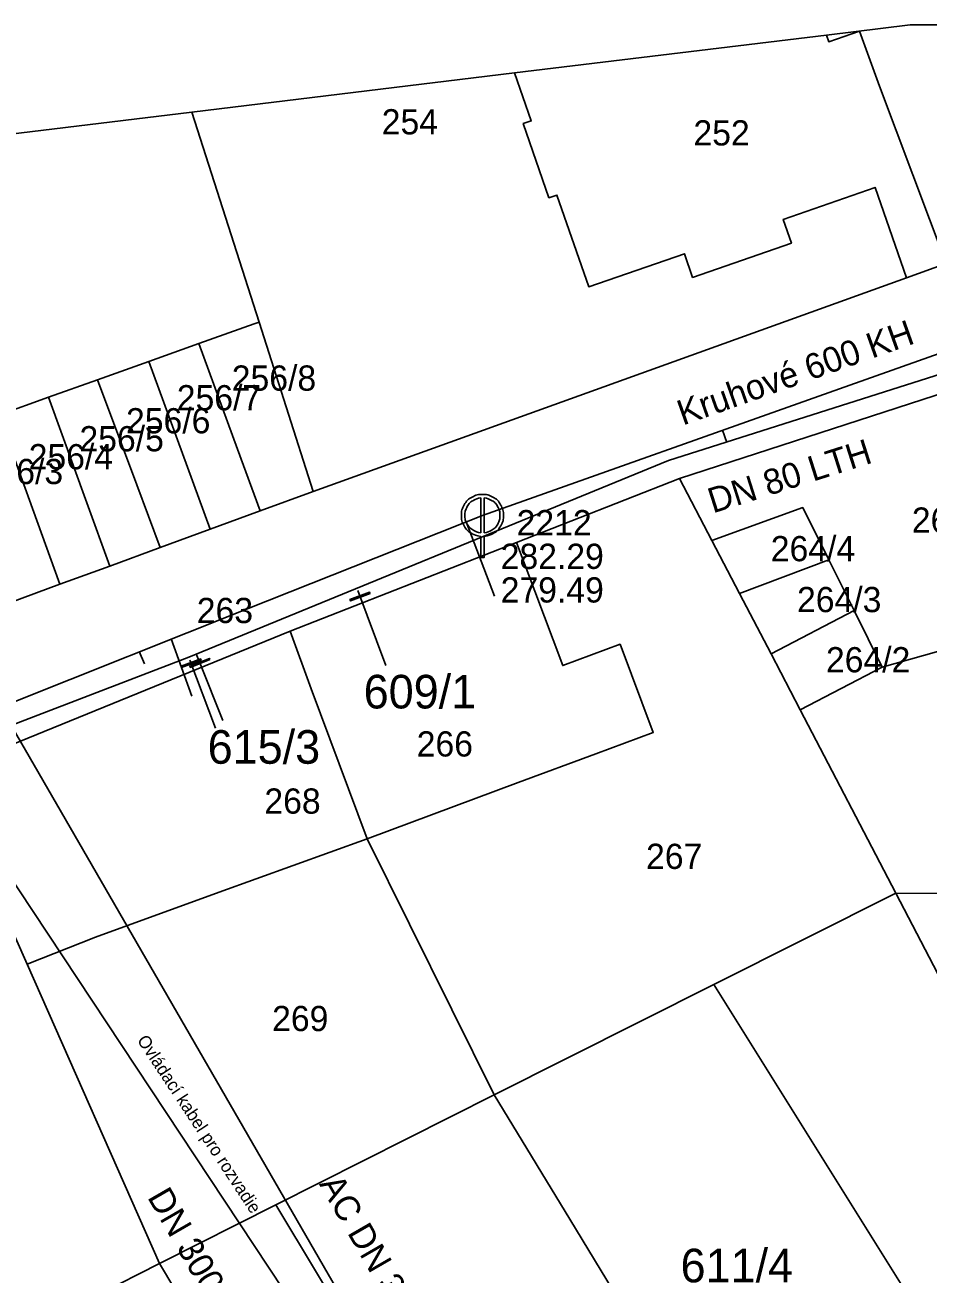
# Model space of a CAD drawing. Extents: x -571312 to -571060, y -1087128 to -1086933.
# Drawn here: x -571207.6 to -571153.9, y -1087007.2 to -1086932.9 of the extents above; entities that cross this region are included whole.
import ezdxf

# ---------------------------------------------------------------- set-up
doc = ezdxf.new("R2010")
doc.units = 0
for name, color, linetype in [('Adresní místo-text', 7, 'Continuous'), ('Armatura vodovodní', 7, 'Continuous'), ('Default', 7, 'Continuous'), ('Elektro NN - vedení', 7, 'Continuous'), ('Elektro VN_ VVN - popis', 7, 'Continuous'), ('Kanalizační přípojka', 7, 'Continuous'), ('Kanalizační stoka', 7, 'Continuous'), ('Kanalizační šachta', 7, 'Continuous'), ('Parcela-polygon', 7, 'Continuous'), ('Parcela-text', 7, 'Continuous'), ('Popis kmenové stoky', 7, 'Continuous'), ('Popis šachty', 7, 'Continuous'), ('Vodovodní přípojka', 7, 'Continuous'), ('Vodovodní řad', 7, 'Continuous'), ('Řad vodovodní popis', 7, 'Continuous')]:
    doc.layers.add(name, color=color, linetype=linetype)

msp = doc.modelspace()

# ---------------------------------------------------------------- linework, layer by layer
at = {"layer": 'Armatura vodovodní'}
for points in [[(-571187.124, -1086966.71), (-571188.295, -1086967.148), (-571188.323, -1086967.075), (-571187.152, -1086966.637), (-571187.124, -1086966.71)], [(-571197.17, -1086970.679), (-571198.342, -1086971.116), (-571198.369, -1086971.043), (-571197.198, -1086970.606), (-571197.17, -1086970.679)], [(-571196.655, -1086970.643), (-571197.817, -1086971.103), (-571197.846, -1086971.03), (-571196.683, -1086970.57), (-571196.655, -1086970.643)]]:
    msp.add_lwpolyline(points, dxfattribs=at)
at = {"layer": 'Default'}
for points in [[(-571180.543, -1086963.308), (-571180.801, -1086963.29), (-571181.063, -1086963.144), (-571181.36, -1086962.98), (-571181.525, -1086962.683), (-571181.69, -1086962.385), (-571181.69, -1086962.06), (-571181.69, -1086961.733), (-571181.522, -1086961.433), (-571181.353, -1086961.132), (-571181.055, -1086960.971), (-571180.757, -1086960.81), (-571180.44, -1086960.81), (-571180.125, -1086960.81), (-571179.826, -1086960.971), (-571179.527, -1086961.132), (-571179.358, -1086961.433), (-571179.19, -1086961.733), (-571179.19, -1086962.06), (-571179.19, -1086962.385), (-571179.355, -1086962.683), (-571179.52, -1086962.98), (-571179.817, -1086963.144), (-571180.079, -1086963.29), (-571180.337, -1086963.308)], [(-571180.543, -1086961.022), (-571180.74, -1086961.039), (-571180.955, -1086961.154), (-571181.204, -1086961.289), (-571181.343, -1086961.539), (-571181.482, -1086961.789), (-571181.482, -1086962.06), (-571181.482, -1086962.331), (-571181.346, -1086962.578), (-571181.209, -1086962.824), (-571180.96, -1086962.961), (-571180.748, -1086963.081), (-571180.543, -1086963.095)], [(-571180.337, -1086963.095), (-571180.132, -1086963.081), (-571179.918, -1086962.961), (-571179.671, -1086962.824), (-571179.534, -1086962.578), (-571179.398, -1086962.331), (-571179.398, -1086962.06), (-571179.398, -1086961.789), (-571179.538, -1086961.539), (-571179.678, -1086961.289), (-571179.927, -1086961.154), (-571180.14, -1086961.039), (-571180.337, -1086961.022)]]:
    msp.add_open_spline(points, degree=3, dxfattribs=at)
at = {"layer": 'Elektro NN - vedení'}
msp.add_lwpolyline([(-571071.926, -1087014.396), (-571073.5, -1087015.707), (-571083.992, -1087003.116), (-571092.911, -1086996.034), (-571095.272, -1086994.46), (-571113.896, -1086998.657), (-571175.538, -1087035.118), (-571177.374, -1087030.659), (-571213.311, -1086976.361), (-571216.983, -1086969.541), (-571228.263, -1086944.884), (-571229.263, -1086941.883)], dxfattribs=at)
at = {"layer": 'Kanalizační přípojka'}
for points in [[(-571165.9, -1086957.73), (-571166.159, -1086956.998)], [(-571179.73, -1086966.87), (-571181.403, -1086962.442)], [(-571197.72, -1086972.82), (-571198.961, -1086969.413)], [(-571200.55, -1086970.9), (-571200.865, -1086970.169)]]:
    msp.add_lwpolyline(points, dxfattribs=at)
at = {"layer": 'Kanalizační stoka'}
for points in [[(-571180.44, -1086962.06), (-571159.195, -1086954.53), (-571137.95, -1086947)], [(-571208.5, -1086973.24), (-571194.47, -1086967.65), (-571180.44, -1086962.06)]]:
    msp.add_lwpolyline(points, dxfattribs=at)
at = {"layer": 'Kanalizační šachta'}
for points in [[(-571180.543, -1086963.095), (-571180.543, -1086961.022)], [(-571180.337, -1086961.022), (-571180.337, -1086963.095)], [(-571180.337, -1086963.308), (-571180.337, -1086964.56), (-571180.543, -1086964.56), (-571180.543, -1086963.308)]]:
    msp.add_lwpolyline(points, dxfattribs=at)
at = {"layer": 'Parcela-polygon'}
for p, q in [((-571154.996, -1086932.879), (-571159.977, -1086933.483)), ((-571122.956, -1086932.879), (-571154.996, -1086932.879)), ((-571159.977, -1086933.483), (-571178.531, -1086935.733)), ((-571178.531, -1086935.733), (-571197.723, -1086938.059)), ((-571197.723, -1086938.059), (-571223.423, -1086941.175))]:
    msp.add_line(p, q, dxfattribs=at)
for points in [[(-571178.531, -1086935.733), (-571177.54, -1086938.59), (-571178.01, -1086938.75), (-571176.49, -1086943.16), (-571176.01, -1086943), (-571174.12, -1086948.46), (-571168.43, -1086946.49), (-571167.94, -1086947.9), (-571162.06, -1086945.86), (-571162.55, -1086944.45), (-571157.09, -1086942.55), (-571155.22, -1086947.92), (-571152.86, -1086947.07), (-571156.82, -1086936.52), (-571158.01, -1086933.25), (-571159.84, -1086933.88), (-571159.977, -1086933.483)], [(-571159.977, -1086933.483), (-571159.84, -1086933.88), (-571158.01, -1086933.25), (-571156.82, -1086936.52), (-571152.86, -1086947.07), (-571140.74, -1086942.7), (-571124.19, -1086936.69), (-571122.956, -1086932.879)], [(-571197.723, -1086938.059), (-571193.73, -1086950.56), (-571190.51, -1086960.64), (-571155.22, -1086947.92), (-571157.09, -1086942.55), (-571162.55, -1086944.45), (-571162.06, -1086945.86), (-571167.94, -1086947.9), (-571168.43, -1086946.49), (-571174.12, -1086948.46), (-571176.01, -1086943), (-571176.49, -1086943.16), (-571178.01, -1086938.75), (-571177.54, -1086938.59), (-571178.531, -1086935.733)], [(-571223.423, -1086941.175), (-571223.15, -1086941.67), (-571214.21, -1086957.87), (-571212.16, -1086957.14), (-571209.22, -1086956.09), (-571206.25, -1086955.03), (-571203.34, -1086954), (-571200.29, -1086952.91), (-571197.31, -1086951.84), (-571194.02, -1086950.67), (-571193.73, -1086950.56), (-571197.723, -1086938.059)], [(-571152.86, -1086947.07), (-571155.22, -1086947.92), (-571190.51, -1086960.64), (-571193.66, -1086961.8), (-571196.64, -1086962.89), (-571199.6, -1086963.98), (-571202.6, -1086965.08), (-571205.57, -1086966.16), (-571208.52, -1086967.25), (-571211.54, -1086968.35), (-571214.64, -1086969.49), (-571219.5, -1086971.02), (-571225.44, -1086972.88), (-571230.87, -1086974.59), (-571232.95, -1086975.24), (-571245.21, -1086979.4), (-571247.22, -1086979.94), (-571250.67, -1086980.27)], [(-571308.971, -1086951.546), (-571306.25, -1086957.27), (-571289.46, -1086969.43), (-571269.48, -1086983.31), (-571253.67, -1086989.56), (-571249.74, -1086991.11), (-571231.55, -1086984.26), (-571212.55, -1086977.39), (-571191.88, -1086968.96), (-571178.41, -1086963.67), (-571168.71, -1086959.87), (-571150.45, -1086953.94)], [(-571149.28, -1086969.01), (-571156.67, -1086971.09), (-571161.54, -1086973.63), (-571155.86, -1086984.54), (-571144.84, -1086984.62)], [(-571144.84, -1086984.62), (-571155.86, -1086984.54), (-571144.15, -1087007.02)]]:
    msp.add_lwpolyline(points, dxfattribs=at)
for points in [[(-571190.51, -1086960.64), (-571193.73, -1086950.56), (-571194.02, -1086950.67), (-571197.31, -1086951.84), (-571195.01, -1086958.13), (-571193.66, -1086961.8)], [(-571200.29, -1086952.91), (-571197.99, -1086959.19), (-571196.64, -1086962.89), (-571193.66, -1086961.8), (-571195.01, -1086958.13), (-571197.31, -1086951.84)], [(-571203.34, -1086954), (-571201, -1086960.25), (-571199.6, -1086963.98), (-571196.64, -1086962.89), (-571197.99, -1086959.19), (-571200.29, -1086952.91)], [(-571206.25, -1086955.03), (-571203.97, -1086961.31), (-571202.6, -1086965.08), (-571199.6, -1086963.98), (-571201, -1086960.25), (-571203.34, -1086954)], [(-571168.71, -1086959.87), (-571166.79, -1086963.56), (-571161.39, -1086961.6), (-571159.84, -1086964.71), (-571158.34, -1086967.73), (-571156.67, -1086971.09), (-571149.28, -1086969.01), (-571150.45, -1086953.94)], [(-571209.22, -1086956.09), (-571206.94, -1086962.36), (-571205.57, -1086966.16), (-571202.6, -1086965.08), (-571203.97, -1086961.31), (-571206.25, -1086955.03)], [(-571212.16, -1086957.14), (-571209.9, -1086963.41), (-571208.52, -1086967.25), (-571205.57, -1086966.16), (-571206.94, -1086962.36), (-571209.22, -1086956.09)], [(-571166.79, -1086963.56), (-571168.71, -1086959.87), (-571178.41, -1086963.67), (-571175.66, -1086971), (-571172.25, -1086969.73), (-571170.28, -1086974.98), (-571173.69, -1086976.25), (-571178.32, -1086977.96), (-571187.29, -1086981.31), (-571179.74, -1086996.54), (-571166.67, -1086989.97), (-571155.86, -1086984.54), (-571161.54, -1086973.63), (-571163.27, -1086970.3), (-571165.15, -1086966.71)], [(-571159.84, -1086964.71), (-571161.39, -1086961.6), (-571166.79, -1086963.56), (-571165.15, -1086966.71)], [(-571178.41, -1086963.67), (-571191.88, -1086968.96), (-571190.63, -1086972.39), (-571187.29, -1086981.31), (-571178.32, -1086977.96), (-571173.69, -1086976.25), (-571170.28, -1086974.98), (-571172.25, -1086969.73), (-571175.66, -1086971)], [(-571158.34, -1086967.73), (-571159.84, -1086964.71), (-571165.15, -1086966.71), (-571163.27, -1086970.3)], [(-571163.27, -1086970.3), (-571161.54, -1086973.63), (-571156.67, -1086971.09), (-571158.34, -1086967.73)], [(-571191.88, -1086968.96), (-571212.55, -1086977.39), (-571211.36, -1086980.09), (-571209.71, -1086983.81), (-571208.98, -1086985.45), (-571207.52, -1086988.77), (-571203.45, -1086987.16), (-571196.09, -1086984.48), (-571187.29, -1086981.31), (-571190.63, -1086972.39)], [(-571187.29, -1086981.31), (-571196.09, -1086984.48), (-571203.45, -1086987.16), (-571207.52, -1086988.77), (-571199.65, -1087006.57), (-571192.72, -1087003.08), (-571179.74, -1086996.54)], [(-571144.15, -1087007.02), (-571155.86, -1086984.54), (-571166.67, -1086989.97), (-571152.8, -1087012.2)], [(-571208.98, -1086985.45), (-571218.36, -1086988.9), (-571217.04, -1086992.42), (-571226.94, -1086996.1), (-571217.97, -1087015.93), (-571206.82, -1087010.23), (-571199.65, -1087006.57), (-571207.52, -1086988.77)], [(-571179.74, -1086996.54), (-571179.19, -1086997.45), (-571175.25, -1087003.94), (-571172.31, -1087008.78), (-571167.11, -1087017.33), (-571165.57, -1087019.85), (-571152.8, -1087012.2), (-571166.67, -1086989.97)], [(-571179.19, -1086997.45), (-571179.74, -1086996.54), (-571192.72, -1087003.08), (-571178.15, -1087027.35), (-571165.57, -1087019.85), (-571167.11, -1087017.33), (-571172.31, -1087008.78), (-571175.25, -1087003.94)], [(-571178.15, -1087027.35), (-571192.72, -1087003.08), (-571199.65, -1087006.57), (-571184.85, -1087031.35)], [(-571184.85, -1087031.35), (-571199.65, -1087006.57), (-571206.82, -1087010.23), (-571202.38, -1087017.63), (-571197.08, -1087017.54), (-571187.38, -1087032.88)]]:
    msp.add_lwpolyline(points, close=True, dxfattribs=at)
at = {"layer": 'Vodovodní přípojka'}
for p, q in [((-571186.19, -1086970.999), (-571187.855, -1086966.54)), ((-571196.325, -1086974.732), (-571197.838, -1086970.678))]:
    msp.add_line(p, q, dxfattribs=at)
msp.add_lwpolyline([(-571197.46, -1086970.307), (-571197.25, -1086970.837), (-571195.891, -1086974.271)], dxfattribs=at)
at = {"layer": 'Vodovodní řad'}
for points in [[(-571259.706, -1087078.885), (-571257.725, -1087077.417), (-571211.542, -1087050.048), (-571176.933, -1087029.184), (-571227.483, -1086941.667)], [(-571118.52, -1087001.2), (-571118.67, -1087000.053), (-571123.745, -1086988.554), (-571132.766, -1086954.96), (-571134.366, -1086951.47), (-571139.458, -1086950.161), (-571144.547, -1086950.9), (-571169.366, -1086958.786), (-571197.91, -1086970.492), (-571213.143, -1086976.341), (-571239.84, -1086984.572), (-571249.273, -1086987.925), (-571267.719, -1086980.097), (-571298.302, -1086956.821), (-571302.312, -1086953.213), (-571303.56, -1086950.89)]]:
    msp.add_lwpolyline(points, dxfattribs=at)

# ---------------------------------------------------------------- texts
at = {"layer": 'Adresní místo-text'}
for s, p in [('609/1', (-571187.505, -1086973.55)), ('615/3', (-571196.785, -1086976.84)), ('611/4', (-571168.655, -1087007.7))]:
    msp.add_text(s, height=2, dxfattribs=at).set_placement(p)
at = {"layer": 'Elektro VN_ VVN - popis'}
msp.add_text('Ovládací kabel pro rozvadie', height=0.75, rotation=303.34029, dxfattribs=at).set_placement((-571201.01, -1086993.29))
at = {"layer": 'Parcela-text'}
for s, p in [('254', (-571186.43, -1086939.39)), ('252', (-571167.89, -1086940.05)), ('256/8', (-571195.35, -1086954.64)), ('256/7', (-571198.62, -1086955.81)), ('256/6', (-571201.64, -1086957.18)), ('256/5', (-571204.41, -1086958.25)), ('256/4', (-571207.43, -1086959.32)), ('256/3', (-571210.4, -1086960.2)), ('265/2', (-571154.9, -1086963.09)), ('264/4', (-571163.29, -1086964.79)), ('264/3', (-571161.73, -1086967.82)), ('263', (-571197.43, -1086968.47)), ('264/2', (-571160.01, -1086971.4)), ('266', (-571184.35, -1086976.41)), ('268', (-571193.41, -1086979.81)), ('267', (-571170.71, -1086983.1)), ('269', (-571192.95, -1086992.75))]:
    msp.add_text(s, height=1.5, dxfattribs=at).set_placement(p)
at = {"layer": 'Popis kmenové stoky'}
msp.add_text('Kruhové 600 KH', height=1.5, rotation=19.51618, dxfattribs=at).set_placement((-571168.522, -1086956.723))
at = {"layer": 'Popis šachty'}
for s, p in [('2212', (-571178.406, -1086963.246)), ('282.29', (-571179.355, -1086965.246)), ('279.49', (-571179.355, -1086967.246))]:
    msp.add_text(s, height=1.5, dxfattribs=at).set_placement(p)
at = {"layer": 'Řad vodovodní popis'}
for s, rotation, p in [('DN 80 LTH', 17.62716, (-571166.735, -1086961.95)), ('AC DN 300', 300.01101, (-571190.179, -1087001.848)), ('DN 300 AC', 300.01101, (-571200.4, -1087002.629))]:
    msp.add_text(s, height=1.5, rotation=rotation, dxfattribs=at).set_placement(p)

doc.saveas('drawing.dxf')
